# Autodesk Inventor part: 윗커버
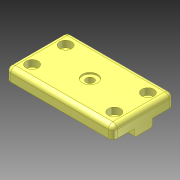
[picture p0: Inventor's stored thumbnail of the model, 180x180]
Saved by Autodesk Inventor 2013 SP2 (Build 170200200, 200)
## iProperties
Created: 2025-04
Part Number: 윗커버
Material: Generic
Document SubType Name: Modeling
Designer: 601
Density: 1 g/cm^3
Author: 601
변환 표준: STEP AP214IS
전처리기: Build: 200, Release: 2013 SP2 Update 6 - Date: Thu 07/17/2014
전송 단위: 밀리미터
불확실성: 0.01
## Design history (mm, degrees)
node "윗커버1"
node "솔리드1"
node "기준1"
